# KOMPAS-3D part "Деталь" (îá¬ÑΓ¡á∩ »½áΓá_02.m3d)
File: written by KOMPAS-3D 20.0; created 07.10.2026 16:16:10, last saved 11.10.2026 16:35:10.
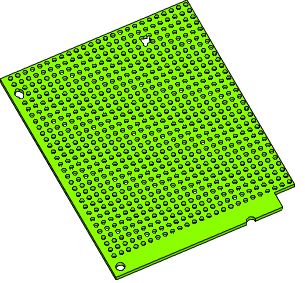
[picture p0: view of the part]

Document properties: Полное имя файла: D:\myProjects\Progect_esp32\box_compas\Макетная плата_02.m3d

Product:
- Part/product: Деталь
    Масса: 0.0468383

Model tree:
1. Эскиз:1
2. Элемент выдавливания:1
     Расстояние 1 = 1.5
3. Эскиз:2  (with: Элемент выдавливания:1)
4. Элемент выдавливания:2
     Расстояние 2 = 1.5
5. Эскиз:3  (with: Элемент выдавливания:1)
6. Элемент выдавливания:3
     Расстояние 2 = 1.5
7. Массив по сетке:1  (with: Элемент выдавливания:3, Эскиз:3, Элемент выдавливания:1)  (775 pattern instances)
     Шаг 1 = 2.54; Угол раствора = -90; Шаг 2 = 2.54
8. Эскиз:4  (with: Элемент выдавливания:1, Элемент выдавливания:2)
9. Элемент выдавливания:4
     Расстояние 2 = 1.5
10. Эскиз:5  (with: Элемент выдавливания:1)
11. Элемент выдавливания:5
     Расстояние 2 = 1.5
